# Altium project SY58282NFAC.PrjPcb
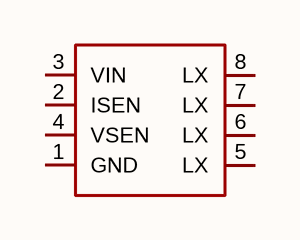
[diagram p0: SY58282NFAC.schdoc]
1 sheet, 1 parts. Net scope: global (net labels, ports and power ports of the same name join across sheets).

## Sheet SY58282NFAC.schdoc
size 127 x 101 mm

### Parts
U?  sy58282nfac  [SOIC-8_L4.9-W3.8-P1.27-LS6.0-BL]  (value not drawn)

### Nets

Not connected (* = marked no-connect by the designer): U? 1(GND) 2(ISEN) 3(VIN) 4(VSEN) 5(LX) 6(LX) 7(LX) 8(LX)

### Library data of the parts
U? = sy58282nfac: 类型:-;工作电压(DC):7V~14.5V;开关频率:200kHz;通道数:1;输出电压:-;输出电流:-;调光:-;拓扑结构:降压;; Manufacturer: Silergy(矽力杰); AddInBom: yes; ModelId: ca0cccb852be401a81142c6d2d7c8054; ModelTransform: 192.913,236.22,0,0,0,0,-0.002,0,0; Frequency - Switching: 200kHz; Number of Channels: 1; Topology: 降压; Switch Tube (Built-In/External): 内置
